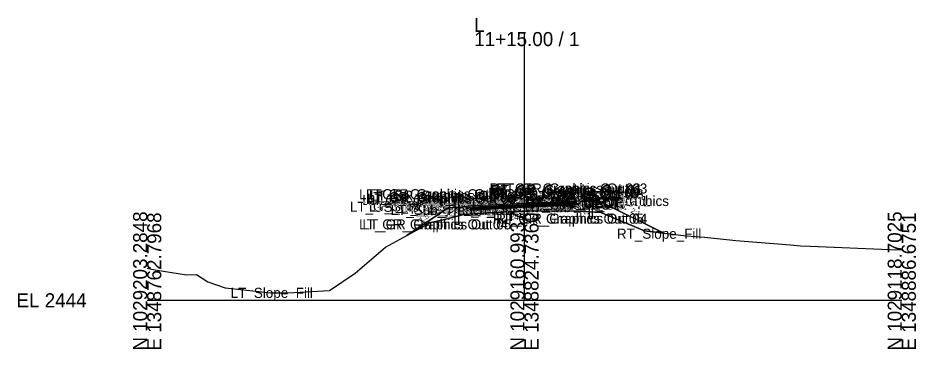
# Model space of a CAD drawing. Extents: x -26 to 1453, y -10 to 4527.
# Drawn here: x 1274.3 to 1452.8, y 990.3 to 1056.2 of the extents above; entities that cross this region are included whole.
import ezdxf

# ---------------------------------------------------------------- set-up
doc = ezdxf.new("R2010")
doc.units = 0
for name, color, linetype in [('Default', 7, 'Continuous'), ('Exist Cross Section Cell', 7, 'Continuous'), ('Exist XS Center Line Elevation Label', 7, 'Continuous'), ('Exist XS Ground Line', 7, 'Continuous'), ('Old_Level_63', 7, 'Continuous'), ('Prop CMT Guardrail Graphics', 7, 'Continuous'), ('Prop CMT Pvmt Course 1', 7, 'Continuous'), ('Prop CMT Pvmt Course 2', 7, 'Continuous'), ('Prop CMT Pvmt Course 3', 7, 'Continuous'), ('Prop CMT Pvmt Surface', 7, 'Continuous'), ('Prop CMT Pvmt Surface Overlay', 7, 'Continuous'), ('Prop CMT Pvmt Surface Shoulder', 7, 'Continuous'), ('Prop CMT Shld Paved Course 1', 7, 'Continuous'), ('Prop CMT Shld Paved Course 2', 7, 'Continuous'), ('Prop CMT Shld Paved Course 3', 7, 'Continuous'), ('Prop CMT Slope Grass', 7, 'Continuous'), ('Prop CMT Subgrade Earthwork', 7, 'Continuous'), ('Prop XS Earthwork Shape', 7, 'Continuous'), ('Prop XS EOT Tick Mark', 7, 'Continuous'), ('Prop XS SE Text', 7, 'Continuous'), ('Prop XS Side Slope Text', 7, 'Continuous')]:
    doc.layers.add(name, color=color, linetype=linetype)

msp = doc.modelspace()

# ---------------------------------------------------------------- linework, layer by layer
at = {"layer": 'Exist Cross Section Cell'}
for p, q in [((1375, 1000), (1375, 1053.38)), ((1300, 1000), (1375, 1000)), ((1375, 1000), (1450, 1000))]:
    msp.add_line(p, q, dxfattribs=at)
at = {"layer": 'Exist XS Ground Line'}
msp.add_lwpolyline([(1300, 1006.39), (1300.86, 1006.21), (1301.97, 1006), (1306.17, 1005.33), (1307.82, 1005.05), (1309.81, 1005.15), (1312.08, 1003.71), (1315.48, 1002.5), (1322.26, 1001.73), (1324.6, 1001.49), (1327.94, 1001.49), (1336.26, 1001.97), (1341.32, 1005.4), (1347.4, 1010.6), (1355.4, 1014.95), (1356.15, 1015.44), (1358.54, 1015.97), (1362.92, 1017.06), (1366.15, 1017.29), (1367.55, 1017.39), (1375, 1017.73), (1375.83, 1017.77), (1376.55, 1017.79), (1385.5, 1017.74), (1386.02, 1017.74), (1386.63, 1017.7), (1390.15, 1017.5), (1398.84, 1013.8), (1407.19, 1012.85), (1410.81, 1012.57), (1413.98, 1012.24), (1417.02, 1011.88), (1427.87, 1011.03), (1429.87, 1010.85), (1431.81, 1010.76), (1447.63, 1010.11), (1450, 1010.06)], dxfattribs=at)
at = {"layer": 'Prop CMT Guardrail Graphics'}
for points in [[(1388.54, 1022.26), (1387.2, 1022.26), (1386.93, 1021.97)], [(1386.93, 1021.97), (1387.2, 1021.68)], [(1387.2, 1021.68), (1386.93, 1021.39)], [(1386.93, 1021.39), (1387.2, 1021.1), (1387.87, 1021.1)], [(1388.54, 1016.26), (1388.54, 1022.26)], [(1361.23, 1015.11), (1361.23, 1021.11)], [(1361.23, 1021.11), (1362.56, 1021.11), (1362.83, 1020.82)], [(1362.83, 1020.24), (1362.56, 1019.94), (1361.89, 1019.94)], [(1361.89, 1019.94), (1361.89, 1015.11)], [(1362.83, 1020.82), (1362.56, 1020.53)], [(1362.56, 1020.53), (1362.83, 1020.24)], [(1387.87, 1021.1), (1387.87, 1016.26)], [(1387.87, 1016.26), (1388.54, 1016.26)], [(1361.89, 1015.11), (1361.23, 1015.11)]]:
    msp.add_lwpolyline(points, dxfattribs=at)
at = {"layer": 'Prop CMT Pvmt Course 1'}
for points in [[(1374.96, 1019.28), (1384.96, 1019.78)], [(1384.96, 1019.53), (1374.96, 1019.03)], [(1384.96, 1019.78), (1384.96, 1019.53)], [(1374.96, 1019.28), (1364.96, 1018.78)], [(1364.96, 1018.53), (1374.96, 1019.03)], [(1364.96, 1018.78), (1364.96, 1018.53)], [(1374.96, 1019.16), (1374.96, 1019.28)], [(1374.96, 1019.16), (1374.96, 1019.28)], [(1374.96, 1019.03), (1374.96, 1019.16), (1374.96, 1019.16)], [(1374.96, 1019.03), (1374.96, 1019.16), (1374.96, 1019.16)]]:
    msp.add_lwpolyline(points, dxfattribs=at)
at = {"layer": 'Prop CMT Pvmt Course 2'}
for points in [[(1374.96, 1019.03), (1384.96, 1019.53)], [(1384.96, 1019.53), (1384.96, 1019.28)], [(1374.96, 1019.03), (1364.96, 1018.53)], [(1364.96, 1018.28), (1374.96, 1018.78)], [(1364.96, 1018.53), (1364.96, 1018.28)], [(1384.96, 1019.28), (1374.96, 1018.78)], [(1374.96, 1018.78), (1374.96, 1019.03)], [(1374.96, 1018.78), (1374.96, 1019.03)]]:
    msp.add_lwpolyline(points, dxfattribs=at)
at = {"layer": 'Prop CMT Pvmt Course 3'}
for points in [[(1374.96, 1018.78), (1364.96, 1018.28)], [(1364.96, 1018.03), (1374.96, 1018.53)], [(1364.96, 1018.28), (1364.96, 1018.03)], [(1374.96, 1018.78), (1384.96, 1019.28)], [(1384.96, 1019.03), (1374.96, 1018.53)], [(1374.96, 1018.53), (1374.96, 1018.78)], [(1374.96, 1018.53), (1374.96, 1018.78)], [(1384.96, 1019.28), (1384.96, 1019.03)]]:
    msp.add_lwpolyline(points, dxfattribs=at)
at = {"layer": 'Prop CMT Pvmt Surface'}
for points in [[(1374.96, 1019.28), (1384.96, 1019.78)], [(1374.96, 1019.28), (1364.96, 1018.78)]]:
    msp.add_lwpolyline(points, dxfattribs=at)
at = {"layer": 'Prop CMT Pvmt Surface Overlay'}
for points in [[(1374.96, 1019.28), (1384.96, 1019.78)], [(1374.96, 1019.28), (1364.96, 1018.78)]]:
    msp.add_lwpolyline(points, dxfattribs=at)
at = {"layer": 'Prop CMT Pvmt Surface Shoulder'}
for points in [[(1384.96, 1019.78), (1384.96, 1019.78)], [(1364.96, 1018.78), (1364.96, 1018.78)]]:
    msp.add_lwpolyline(points, dxfattribs=at)
at = {"layer": 'Prop CMT Shld Paved Course 1'}
for points in [[(1384.96, 1019.78), (1384.96, 1019.78), (1385.2, 1019.54)], [(1384.96, 1019.53), (1384.96, 1019.78)], [(1385.2, 1019.54), (1384.96, 1019.53)], [(1364.96, 1018.78), (1364.96, 1018.78), (1364.7, 1018.52)], [(1364.7, 1018.52), (1364.96, 1018.53)], [(1364.96, 1018.53), (1364.96, 1018.78)]]:
    msp.add_lwpolyline(points, dxfattribs=at)
at = {"layer": 'Prop CMT Shld Paved Course 2'}
for points in [[(1384.96, 1019.53), (1385.2, 1019.54), (1385.43, 1019.31)], [(1384.96, 1019.28), (1384.96, 1019.53)], [(1364.96, 1018.53), (1364.7, 1018.52), (1364.43, 1018.26)], [(1364.43, 1018.26), (1364.96, 1018.28)], [(1364.96, 1018.28), (1364.96, 1018.53)], [(1385.43, 1019.31), (1384.96, 1019.28)]]:
    msp.add_lwpolyline(points, dxfattribs=at)
at = {"layer": 'Prop CMT Shld Paved Course 3'}
for points in [[(1364.43, 1018.26), (1364.17, 1017.99)], [(1364.17, 1017.99), (1364.96, 1018.03)], [(1364.96, 1018.28), (1364.43, 1018.26)], [(1364.43, 1018.26), (1364.43, 1018.26)], [(1364.96, 1018.03), (1364.96, 1018.28)], [(1384.96, 1019.28), (1385.43, 1019.31)], [(1384.96, 1019.03), (1384.96, 1019.28)], [(1385.67, 1019.07), (1384.96, 1019.03)], [(1385.43, 1019.31), (1385.43, 1019.31)], [(1385.43, 1019.31), (1385.67, 1019.07)]]:
    msp.add_lwpolyline(points, dxfattribs=at)
at = {"layer": 'Prop CMT Slope Grass'}
for points in [[(1384.96, 1019.78), (1386.93, 1019.76)], [(1386.93, 1019.76), (1389.93, 1019.73)], [(1389.93, 1019.73), (1402.67, 1013.36)], [(1359.83, 1018.37), (1351.6, 1012.89)], [(1362.83, 1018.61), (1359.83, 1018.37)], [(1364.96, 1018.78), (1362.83, 1018.61)]]:
    msp.add_lwpolyline(points, dxfattribs=at)
at = {"layer": 'Prop CMT Subgrade Earthwork'}
for points in [[(1385.67, 1019.07), (1386.37, 1019.77)], [(1364.17, 1017.99), (1363.5, 1018.67)], [(1364.96, 1018.03), (1364.17, 1017.99)], [(1374.96, 1018.53), (1364.96, 1018.03)], [(1374.96, 1018.53), (1384.96, 1019.03)], [(1384.96, 1019.03), (1385.67, 1019.07)]]:
    msp.add_lwpolyline(points, dxfattribs=at)
at = {"layer": 'Prop XS Earthwork Shape'}
for points in [[(1386.37, 1019.77), (1386.93, 1019.76), (1389.93, 1019.73), (1402.67, 1013.36), (1398.84, 1013.8), (1390.15, 1017.5), (1386.63, 1017.7), (1386.02, 1017.74), (1385.5, 1017.74), (1376.55, 1017.79), (1375.83, 1017.77), (1375, 1017.73), (1367.55, 1017.39), (1366.15, 1017.29), (1362.92, 1017.06), (1358.54, 1015.97), (1356.15, 1015.44), (1355.4, 1014.95), (1351.6, 1012.89), (1359.83, 1018.37), (1362.83, 1018.61), (1363.5, 1018.67), (1364.17, 1017.99), (1364.96, 1018.03), (1374.96, 1018.53), (1384.96, 1019.03), (1385.67, 1019.07)], [(1362.83, 1018.61), (1359.83, 1018.37), (1351.6, 1012.89), (1355.4, 1014.95), (1356.15, 1015.44), (1358.54, 1015.97), (1362.92, 1017.06), (1366.15, 1017.29), (1367.55, 1017.39), (1375, 1017.73), (1375.83, 1017.77), (1376.55, 1017.79), (1385.5, 1017.74), (1386.02, 1017.74), (1386.63, 1017.7), (1390.15, 1017.5), (1398.84, 1013.8), (1402.67, 1013.36), (1389.93, 1019.73), (1386.93, 1019.76), (1386.37, 1019.77), (1385.67, 1019.07), (1384.96, 1019.03), (1374.96, 1018.53), (1364.96, 1018.03), (1364.17, 1017.99), (1363.5, 1018.67)]]:
    msp.add_lwpolyline(points, close=True, dxfattribs=at)
at = {"layer": 'Prop XS EOT Tick Mark'}
for points in [[(1364.96, 1018.78), (1364.96, 1019.78)], [(1384.96, 1019.78), (1384.96, 1020.78)]]:
    msp.add_lwpolyline(points, dxfattribs=at)

# ---------------------------------------------------------------- texts
at = {"layer": 'Default'}
msp.add_text('-', height=0.0001, dxfattribs=at).set_placement((1300, 1000))
at = {"layer": 'Exist Cross Section Cell'}
for s, p in [('L', (1365, 1053.38)), ('11+15.00 / 1', (1365, 1050.58)), ('EL 2444', (1274, 998.6))]:
    msp.add_text(s, height=2.8, dxfattribs=at).set_placement(p)
for s, p in [('N 1029203.2848', (1300, 990)), ('E 1348762.7968', (1302.8, 990)), ('N 1029160.9937', (1375, 990)), ('E 1348824.7360', (1377.8, 990)), ('N 1029118.7025', (1450, 990)), ('E 1348886.6751', (1452.8, 990))]:
    msp.add_text(s, height=2.8, rotation=90, dxfattribs=at).set_placement(p)
at = {"layer": 'Exist XS Center Line Elevation Label'}
msp.add_text('2461.73', height=1.23, dxfattribs=at).set_placement((1372.05, 1016))
at = {"layer": 'Old_Level_63'}
for s, p in [('RT_GR_Graphics Out 02', (1368.05, 1021.26)), ('RT_GR_Graphics Out 01', (1368.35, 1020.97)), ('RT_GR_Graphics Out 03', (1369.39, 1021.26)), ('LT_GR_Graphics Out 03', (1342.12, 1020.11)), ('LT_GR_Graphics Out 02', (1343.46, 1020.11)), ('LT_GR_Graphics Out 09', (1343.46, 1019.53)), ('LT_GR_Graphics Out 08', (1343.73, 1019.24)), ('LT_GR_Graphics Out 01', (1344.29, 1019.82)), ('RT_GR_Graphics Out 08', (1367.78, 1020.39)), ('RT_GR_Graphics Out 09', (1368.05, 1020.68)), ('RT_GR_Graphics Out 07', (1368.05, 1020.1)), ('RT_GR_Graphics Out 06', (1368.67, 1020.1)), ('RT_TM_OEOT', (1375.85, 1019.78)), ('LT_GS_OS_GR_Face_Graphics', (1340.29, 1017.61)), ('LT_GR_Graphics Out 06', (1342.74, 1018.94)), ('LT_GR_Graphics Out 07', (1343.46, 1018.94)), ('LT_Sub_Trench_Out_DLT', (1344.06, 1017.67)), ('LT_PS2_OEOP', (1354.93, 1017.52)), ('LT_PV2_OEOT', (1355.13, 1017.53)), ('LT_PV1_OEOT', (1355.7, 1017.78)), ('LT_PS1_OEOP', (1355.76, 1017.78)), ('LT_TM_OEOT', (1355.9, 1018.78)), ('RT_PV1_OEEOP_W', (1362.9, 1018.16)), ('LT_PV1_OEEOP_W', (1362.94, 1018.16)), ('RT_Sub_OEEOP', (1364.12, 1017.53)), ('LT_Sub_OEEOP', (1364.17, 1017.53)), ('RT_PV2_OEEOP', (1364.22, 1018.03)), ('RT_PV3_OEEOP', (1364.22, 1017.78)), ('LT_PV2_OEEOP', (1364.27, 1018.03)), ('LT_PV3_OEEOP', (1364.27, 1017.78)), ('RT_GS_OS_GR_Face_Graphics', (1364.34, 1018.76)), ('RT_Sub_Trench_Out_DLT', (1366.89, 1018.77)), ('PV1_PGL_W', (1367.54, 1018.16)), ('PV1_PGL', (1369.43, 1018.28)), ('RT_Sub_Trench_Out', (1369.83, 1018.07)), ('RT_PS3_Shelf_Out', (1371.37, 1018.31)), ('RT_Sub_OEOT', (1374.99, 1018.03)), ('RT_PV2_OEOT', (1375.08, 1018.53)), ('RT_PV3_OEOT', (1375.08, 1018.28)), ('RT_PS2_OEOP', (1375.38, 1018.54)), ('RT_PS3_OEOP', (1375.62, 1018.31)), ('RT_PV1_OEOT', (1375.65, 1018.78)), ('RT_PS1_OEOP', (1375.71, 1018.78)), ('RT_GS_OS_CTL', (1379.25, 1018.73)), ('LT_Sub_Trench_Out', (1348.37, 1016.99)), ('LT_GS_OS_CTL', (1349.2, 1017.37)), ('LT_PS3_Shelf_Out', (1350.42, 1017.26)), ('LT_PS3_OEOP', (1354.67, 1017.26)), ('LT_Sub_OEOT', (1355.04, 1017.03)), ('LT_PV3_OEOT', (1355.13, 1017.28)), ('LT_GR_Graphics Out 04', (1342.12, 1014.11)), ('LT_GR_Graphics Out 05', (1342.79, 1014.11)), ('RT_GR_Graphics Out 05', (1368.72, 1015.26)), ('RT_GR_Graphics Out 04', (1369.39, 1015.26)), ('RT_Slope_Fill', (1393.37, 1012.25)), ('LT_Slope_Fill', (1316.59, 1000.49))]:
    msp.add_text(s, height=2, dxfattribs=at).set_placement(p)
at = {"layer": 'Prop XS SE Text'}
for p in [(1378.16, 1020.44), (1368.16, 1019.94)]:
    msp.add_text('0.050', height=1, rotation=2.8628, dxfattribs=at).set_placement(p)
at = {"layer": 'Prop XS Side Slope Text'}
for s, rotation, p in [('1.5:1', 33.6901, (1354.5, 1015.44)), ('2:1', 333.4321, (1396.04, 1017.52))]:
    msp.add_text(s, height=1, rotation=rotation, dxfattribs=at).set_placement(p)

doc.saveas('drawing.dxf')
